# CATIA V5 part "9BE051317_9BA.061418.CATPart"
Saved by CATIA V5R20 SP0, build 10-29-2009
Part number: 9BE051317_9BA.061418
Revision: ANY
Definition: UNKNOWN
Nomenclature: 9BE051317_9BA.061418
Source: Unknown
Bounding box of the stored display mesh (mm): x -8.5 to 8.5, y 0 to 25.5, z -8.5 to 8.5
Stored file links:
  C:\Users\Utente\Desktop\IO LAVORO\3D X SITO CF\CUMSA\3D files BE\BE 051317\9BE051317_9BA.061418.CATPart
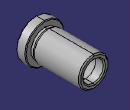
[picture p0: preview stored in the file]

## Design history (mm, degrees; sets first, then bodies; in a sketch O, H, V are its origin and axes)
Body1 "Chaflán4" (main body)
  Solid1: solid without history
